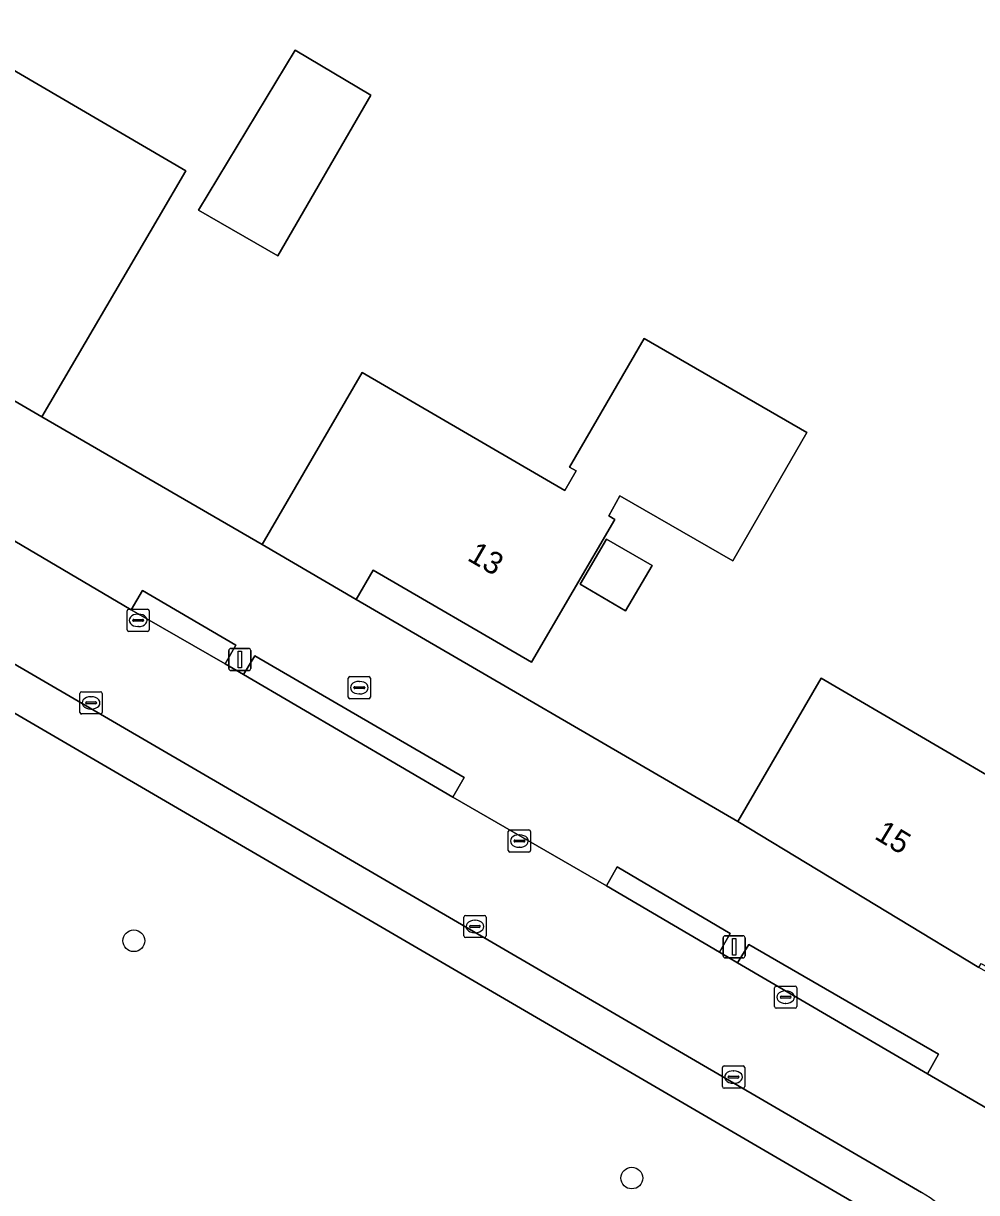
# Model space of a CAD drawing. Extents: x 156502 to 159075, y 384229 to 386100.
# Drawn here: x 157152.9 to 157195.8, y 385865.1 to 385917.7 of the extents above; entities that cross this region are included whole.
import ezdxf

# ---------------------------------------------------------------- set-up
doc = ezdxf.new("R2010")
doc.units = 0
for name, color, linetype in [('IMGEO_Boom', 7, 'Continuous'), ('IMGEO_Erf', 7, 'Continuous'), ('IMGEO_Groenvoorziening', 7, 'Continuous'), ('IMGEO_Haag', 7, 'Continuous'), ('IMGEO_Hek', 7, 'Continuous'), ('IMGEO_Kolk', 7, 'Continuous'), ('IMGEO_Lichtmast', 7, 'Continuous'), ('IMGEO_Pand', 7, 'Continuous'), ('IMGEO_Pand_nummerreeks', 7, 'Continuous'), ('IMGEO_Parkeervlak_open', 7, 'Continuous'), ('IMGEO_Rijbaan_lokaal_open', 7, 'Continuous'), ('IMGEO_Rioolput', 7, 'Continuous'), ('IMGEO_Voetpad_open', 7, 'Continuous')]:
    doc.layers.add(name, color=color, linetype=linetype)

msp = doc.modelspace()

# ---------------------------------------------------------------- linework, layer by layer
at = {"layer": 'IMGEO_Boom'}
for centre in [(157157.909, 385876.436), (157180.326, 385865.757)]:
    msp.add_circle(centre, 0.489, dxfattribs=at)
at = {"layer": 'IMGEO_Erf'}
msp.add_lwpolyline([(157148.886, 385917.721), (157160.243, 385911.082), (157159, 385908.955), (157153.769, 385900.007), (157163.686, 385894.272), (157168.192, 385902.015), (157177.313, 385896.706), (157177.822, 385897.585), (157177.527, 385897.755), (157180.877, 385903.546), (157188.204, 385899.308), (157184.874, 385893.54), (157179.785, 385896.459), (157179.286, 385895.561), (157179.562, 385895.399), (157175.806, 385888.97), (157168.68, 385893.106), (157167.911, 385891.794), (157185.093, 385881.809), (157188.853, 385888.249), (157197.887, 385882.973)], dxfattribs=at)
for points in [[(157164.388, 385907.266), (157160.82, 385909.313), (157165.166, 385916.522), (157168.575, 385914.494)], [(157180.048, 385891.283), (157178.006, 385892.477), (157179.194, 385894.511), (157181.237, 385893.318)]]:
    msp.add_lwpolyline(points, close=True, dxfattribs=at)
at = {"layer": 'IMGEO_Groenvoorziening'}
msp.add_lwpolyline([(157192.564, 385863.354), (157138.908, 385894.614)], dxfattribs=at)
for points in [[(157162.018, 385888.901), (157162.501, 385889.733), (157158.298, 385892.2), (157157.792, 385891.329)], [(157172.275, 385882.9), (157172.777, 385883.778), (157163.363, 385889.258), (157162.851, 385888.415)], [(157184.271, 385875.92), (157184.758, 385876.767), (157179.666, 385879.755), (157179.189, 385878.901)], [(157193.644, 385870.453), (157194.131, 385871.332), (157185.6, 385876.273), (157185.088, 385875.436)]]:
    msp.add_lwpolyline(points, close=True, dxfattribs=at)
at = {"layer": 'IMGEO_Haag'}
for points in [[(157162.018, 385888.901), (157162.501, 385889.733), (157158.298, 385892.2), (157157.792, 385891.329)], [(157172.275, 385882.9), (157172.777, 385883.778), (157163.363, 385889.258), (157162.851, 385888.415)], [(157184.271, 385875.92), (157184.758, 385876.767), (157179.666, 385879.755), (157179.189, 385878.901)], [(157193.644, 385870.453), (157194.131, 385871.332), (157185.6, 385876.273), (157185.088, 385875.436)]]:
    msp.add_lwpolyline(points, close=True, dxfattribs=at)
at = {"layer": 'IMGEO_Hek'}
for points in [[(157153.769, 385900.007), (157163.686, 385894.272)], [(157167.911, 385891.794), (157185.093, 385881.809)]]:
    msp.add_lwpolyline(points, dxfattribs=at)
at = {"layer": 'IMGEO_Kolk'}
for p, q in [((157157.601, 385890.429), (157157.601, 385891.281)), ((157157.676, 385891.355), (157158.528, 385891.355)), ((157157.86, 385890.849), (157157.86, 385890.861)), ((157157.903, 385890.898), (157158.301, 385890.898)), ((157158.089, 385891.135), (157158.114, 385891.135)), ((157158.344, 385890.861), (157158.344, 385890.849)), ((157158.602, 385891.281), (157158.602, 385890.429)), ((157158.528, 385890.355), (157157.676, 385890.355)), ((157158.298, 385890.812), (157157.9, 385890.812)), ((157158.112, 385890.575), (157158.087, 385890.575)), ((157155.482, 385886.714), (157155.482, 385887.566)), ((157155.557, 385887.64), (157156.409, 385887.64)), ((157155.784, 385887.183), (157156.182, 385887.183)), ((157155.97, 385887.42), (157155.995, 385887.42)), ((157156.483, 385887.566), (157156.483, 385886.714)), ((157156.409, 385886.64), (157155.557, 385886.64)), ((157155.741, 385887.134), (157155.741, 385887.146)), ((157156.179, 385887.097), (157155.781, 385887.097)), ((157155.993, 385886.86), (157155.968, 385886.86)), ((157156.225, 385887.146), (157156.225, 385887.134)), ((157174.839, 385881.423), (157175.691, 385881.423)), ((157174.764, 385880.497), (157174.764, 385881.349)), ((157175.023, 385880.917), (157175.023, 385880.929)), ((157175.461, 385880.88), (157175.063, 385880.88)), ((157175.066, 385880.966), (157175.464, 385880.966)), ((157175.252, 385881.203), (157175.277, 385881.203)), ((157175.507, 385880.929), (157175.507, 385880.917)), ((157175.765, 385881.349), (157175.765, 385880.497)), ((157175.691, 385880.423), (157174.839, 385880.423)), ((157175.275, 385880.643), (157175.25, 385880.643)), ((157172.764, 385876.65), (157172.764, 385877.502)), ((157172.839, 385877.576), (157173.691, 385877.576)), ((157173.252, 385877.356), (157173.277, 385877.356)), ((157173.765, 385877.502), (157173.765, 385876.65)), ((157173.023, 385877.07), (157173.023, 385877.082)), ((157173.461, 385877.033), (157173.063, 385877.033)), ((157173.066, 385877.119), (157173.464, 385877.119)), ((157173.275, 385876.796), (157173.25, 385876.796)), ((157173.507, 385877.082), (157173.507, 385877.07)), ((157173.691, 385876.576), (157172.839, 385876.576)), ((157186.751, 385873.47), (157186.751, 385874.322)), ((157186.826, 385874.396), (157187.678, 385874.396)), ((157187.239, 385874.176), (157187.264, 385874.176)), ((157187.752, 385874.322), (157187.752, 385873.47)), ((157187.01, 385873.89), (157187.01, 385873.902)), ((157187.448, 385873.853), (157187.05, 385873.853)), ((157187.053, 385873.939), (157187.451, 385873.939)), ((157187.262, 385873.616), (157187.237, 385873.616)), ((157187.494, 385873.902), (157187.494, 385873.89)), ((157187.678, 385873.396), (157186.826, 385873.396)), ((157184.407, 385869.875), (157184.407, 385870.727)), ((157184.482, 385870.801), (157185.334, 385870.801)), ((157184.709, 385870.344), (157185.107, 385870.344)), ((157184.895, 385870.581), (157184.92, 385870.581)), ((157185.408, 385870.727), (157185.408, 385869.875)), ((157185.334, 385869.801), (157184.482, 385869.801)), ((157184.666, 385870.295), (157184.666, 385870.307)), ((157185.104, 385870.258), (157184.706, 385870.258)), ((157184.918, 385870.021), (157184.893, 385870.021)), ((157185.15, 385870.307), (157185.15, 385870.295))]:
    msp.add_line(p, q, dxfattribs=at)
for points in [[(157157.601, 385890.429), (157157.601, 385891.281)], [(157157.676, 385891.355), (157158.528, 385891.355)], [(157158.602, 385891.281), (157158.602, 385890.429)], [(157158.528, 385890.355), (157157.676, 385890.355)], [(157155.482, 385886.714), (157155.482, 385887.566)], [(157155.557, 385887.64), (157156.409, 385887.64)], [(157156.483, 385887.566), (157156.483, 385886.714)], [(157156.409, 385886.64), (157155.557, 385886.64)], [(157174.839, 385881.423), (157175.691, 385881.423)], [(157174.764, 385880.497), (157174.764, 385881.349)], [(157175.765, 385881.349), (157175.765, 385880.497)], [(157175.691, 385880.423), (157174.839, 385880.423)], [(157172.764, 385876.65), (157172.764, 385877.502)], [(157172.839, 385877.576), (157173.691, 385877.576)], [(157173.765, 385877.502), (157173.765, 385876.65)], [(157173.691, 385876.576), (157172.839, 385876.576)], [(157186.751, 385873.47), (157186.751, 385874.322)], [(157186.826, 385874.396), (157187.678, 385874.396)], [(157187.752, 385874.322), (157187.752, 385873.47)], [(157187.678, 385873.396), (157186.826, 385873.396)], [(157184.407, 385869.875), (157184.407, 385870.727)], [(157184.482, 385870.801), (157185.334, 385870.801)], [(157185.408, 385870.727), (157185.408, 385869.875)], [(157185.334, 385869.801), (157184.482, 385869.801)]]:
    msp.add_lwpolyline(points, dxfattribs=at)
for centre, radius, start, end in [((157157.678, 385891.279), 0.0765, 91.552, 178.448), ((157157.678, 385891.279), 0.0765, 91.552, 178.448), ((157157.9, 385890.858), 0.0403, 85.8775, 175.7526), ((157157.897, 385890.848), 0.0366, 178.938, 274.7102), ((157158.301, 385890.855), 0.043, 264.8664, 352.4533), ((157158.305, 385890.86), 0.0386, 1.7309, 96.639), ((157158.526, 385891.279), 0.0765, 1.552, 88.448), ((157158.526, 385891.279), 0.0765, 1.552, 88.448), ((157157.678, 385890.431), 0.0765, 181.552, 268.448), ((157157.678, 385890.431), 0.0765, 181.552, 268.448), ((157158.526, 385890.431), 0.0765, 271.552, 358.448), ((157158.526, 385890.431), 0.0765, 271.552, 358.448), ((157155.559, 385887.564), 0.0765, 91.552, 178.448), ((157155.559, 385887.564), 0.0765, 91.552, 178.448), ((157155.781, 385887.143), 0.0403, 85.8775, 175.7526), ((157156.186, 385887.145), 0.0386, 1.7309, 96.639), ((157156.407, 385887.564), 0.0765, 1.552, 88.448), ((157156.407, 385887.564), 0.0765, 1.552, 88.448), ((157155.559, 385886.716), 0.0765, 181.552, 268.448), ((157155.559, 385886.716), 0.0765, 181.552, 268.448), ((157155.778, 385887.133), 0.0366, 178.938, 274.7102), ((157156.182, 385887.14), 0.043, 264.8664, 352.4533), ((157156.407, 385886.716), 0.0765, 271.552, 358.448), ((157156.407, 385886.716), 0.0765, 271.552, 358.448), ((157174.841, 385881.347), 0.0765, 91.552, 178.448), ((157174.841, 385881.347), 0.0765, 91.552, 178.448), ((157175.689, 385881.347), 0.0765, 1.552, 88.448), ((157175.689, 385881.347), 0.0765, 1.552, 88.448), ((157175.063, 385880.926), 0.0403, 85.8775, 175.7526), ((157175.06, 385880.916), 0.0366, 178.938, 274.7102), ((157175.464, 385880.923), 0.043, 264.8664, 352.4533), ((157175.468, 385880.928), 0.0386, 1.7309, 96.639), ((157174.841, 385880.499), 0.0765, 181.552, 268.448), ((157174.841, 385880.499), 0.0765, 181.552, 268.448), ((157175.689, 385880.499), 0.0765, 271.552, 358.448), ((157175.689, 385880.499), 0.0765, 271.552, 358.448), ((157172.841, 385877.5), 0.0765, 91.552, 178.448), ((157172.841, 385877.5), 0.0765, 91.552, 178.448), ((157173.689, 385877.5), 0.0765, 1.552, 88.448), ((157173.689, 385877.5), 0.0765, 1.552, 88.448), ((157172.841, 385876.652), 0.0765, 181.552, 268.448), ((157172.841, 385876.652), 0.0765, 181.552, 268.448), ((157173.063, 385877.079), 0.0403, 85.8775, 175.7526), ((157173.06, 385877.069), 0.0366, 178.938, 274.7102), ((157173.464, 385877.076), 0.043, 264.8664, 352.4533), ((157173.468, 385877.081), 0.0386, 1.7309, 96.639), ((157173.689, 385876.652), 0.0765, 271.552, 358.448), ((157173.689, 385876.652), 0.0765, 271.552, 358.448), ((157186.828, 385874.32), 0.0765, 91.552, 178.448), ((157186.828, 385874.32), 0.0765, 91.552, 178.448), ((157187.676, 385874.32), 0.0765, 1.552, 88.448), ((157187.676, 385874.32), 0.0765, 1.552, 88.448), ((157187.05, 385873.899), 0.0403, 85.8775, 175.7526), ((157187.047, 385873.889), 0.0366, 178.938, 274.7102), ((157187.451, 385873.896), 0.043, 264.8664, 352.4533), ((157187.455, 385873.901), 0.0386, 1.7309, 96.639), ((157186.828, 385873.472), 0.0765, 181.552, 268.448), ((157186.828, 385873.472), 0.0765, 181.552, 268.448), ((157187.676, 385873.472), 0.0765, 271.552, 358.448), ((157187.676, 385873.472), 0.0765, 271.552, 358.448), ((157184.484, 385870.725), 0.0765, 91.552, 178.448), ((157184.484, 385870.725), 0.0765, 91.552, 178.448), ((157184.706, 385870.304), 0.0403, 85.8775, 175.7526), ((157185.111, 385870.306), 0.0386, 1.7309, 96.639), ((157185.332, 385870.725), 0.0765, 1.552, 88.448), ((157185.332, 385870.725), 0.0765, 1.552, 88.448), ((157184.484, 385869.877), 0.0765, 181.552, 268.448), ((157184.484, 385869.877), 0.0765, 181.552, 268.448), ((157184.703, 385870.294), 0.0366, 178.938, 274.7102), ((157185.107, 385870.301), 0.043, 264.8664, 352.4533), ((157185.332, 385869.877), 0.0765, 271.552, 358.448), ((157185.332, 385869.877), 0.0765, 271.552, 358.448)]:
    msp.add_arc(centre, radius, start, end, dxfattribs=at)
for centre, major_axis, ratio, start_param, end_param in [((157158.088, 385890.855), (-0.387, 0.002), 0.722429, 4.712389, 7.853982), ((157158.113, 385890.855), (-0.39, 0.002), 0.717154, 1.570796, 4.712389), ((157155.969, 385887.14), (-0.387, 0.002), 0.722429, 4.712389, 7.853982), ((157155.994, 385887.14), (-0.39, 0.002), 0.717154, 1.570796, 4.712389), ((157175.251, 385880.923), (-0.387, 0.002), 0.722429, 4.712389, 7.853982), ((157175.276, 385880.923), (-0.39, 0.002), 0.717154, 1.570796, 4.712389), ((157173.251, 385877.076), (-0.387, 0.002), 0.722429, 4.712389, 7.853982), ((157173.276, 385877.076), (-0.39, 0.002), 0.717154, 1.570796, 4.712389), ((157187.238, 385873.896), (-0.387, 0.002), 0.722429, 4.712389, 7.853982), ((157187.263, 385873.896), (-0.39, 0.002), 0.717154, 1.570796, 4.712389), ((157184.894, 385870.301), (-0.387, 0.002), 0.722429, 4.712389, 7.853982), ((157184.919, 385870.301), (-0.39, 0.002), 0.717154, 1.570796, 4.712389)]:
    msp.add_ellipse(centre, major_axis=major_axis, ratio=ratio, start_param=start_param, end_param=end_param, dxfattribs=at)
at = {"layer": 'IMGEO_Lichtmast'}
for p, q in [((157162.179, 385888.692), (157162.179, 385889.492)), ((157162.179, 385889.492), (157162.179, 385888.692)), ((157162.279, 385889.592), (157163.069, 385889.592)), ((157163.069, 385889.592), (157162.279, 385889.592)), ((157163.169, 385889.492), (157163.169, 385888.692)), ((157163.169, 385888.692), (157163.169, 385889.492)), ((157163.069, 385888.592), (157162.279, 385888.592)), ((157162.279, 385888.592), (157163.069, 385888.592)), ((157184.534, 385876.66), (157185.324, 385876.66)), ((157185.324, 385876.66), (157184.534, 385876.66)), ((157184.434, 385875.76), (157184.434, 385876.56)), ((157184.434, 385876.56), (157184.434, 385875.76)), ((157185.424, 385876.56), (157185.424, 385875.76)), ((157185.424, 385875.76), (157185.424, 385876.56)), ((157185.324, 385875.66), (157184.534, 385875.66)), ((157184.534, 385875.66), (157185.324, 385875.66))]:
    msp.add_line(p, q, dxfattribs=at)
for points in [[(157162.599, 385889.467), (157162.749, 385889.467), (157162.749, 385888.717), (157162.599, 385888.717), (157162.599, 385889.467)], [(157184.854, 385876.535), (157185.004, 385876.535), (157185.004, 385875.785), (157184.854, 385875.785), (157184.854, 385876.535)]]:
    msp.add_lwpolyline(points, dxfattribs=at)
for centre, start, end in [((157162.279, 385889.492), 90, 180), ((157162.279, 385889.492), 90, 180), ((157163.069, 385889.492), 0, 90), ((157163.069, 385889.492), 360, 90), ((157162.279, 385888.692), 180, 270), ((157162.279, 385888.692), 180, 270), ((157163.069, 385888.692), 270, 0), ((157163.069, 385888.692), 270, 0), ((157184.534, 385876.56), 90, 180), ((157184.534, 385876.56), 90, 180), ((157185.324, 385876.56), 0, 90), ((157185.324, 385876.56), 360, 90), ((157184.534, 385875.76), 180, 270), ((157184.534, 385875.76), 180, 270), ((157185.324, 385875.76), 270, 0), ((157185.324, 385875.76), 270, 0)]:
    msp.add_arc(centre, 0.1, start, end, dxfattribs=at)
at = {"layer": 'IMGEO_Pand'}
for points in [[(157159, 385908.955), (157160.243, 385911.082), (157148.886, 385917.721), (157146.148, 385913.037), (157142.433, 385906.61), (157153.769, 385900.007)], [(157164.388, 385907.266), (157168.575, 385914.494), (157165.166, 385916.522), (157160.82, 385909.313)], [(157163.686, 385894.272), (157167.911, 385891.794), (157168.68, 385893.106), (157175.806, 385888.97), (157179.562, 385895.399), (157179.286, 385895.561), (157179.785, 385896.459), (157184.874, 385893.54), (157188.204, 385899.308), (157180.877, 385903.546), (157177.527, 385897.755), (157177.822, 385897.585), (157177.313, 385896.706), (157168.192, 385902.015)], [(157179.194, 385894.511), (157178.006, 385892.477), (157180.048, 385891.283), (157181.237, 385893.318)], [(157195.952, 385875.233), (157196.06, 385875.413), (157196.439, 385875.192), (157200.198, 385881.649), (157199.904, 385881.82), (157200.407, 385882.684), (157205.225, 385879.893), (157209.465, 385887.215), (157202.417, 385891.356), (157198.106, 385884.017), (157198.399, 385883.845), (157197.887, 385882.973), (157188.853, 385888.249), (157185.093, 385881.809)]]:
    msp.add_lwpolyline(points, close=True, dxfattribs=at)
at = {"layer": 'IMGEO_Parkeervlak_open'}
for points in [[(157193.373, 385865.1), (157139.856, 385896.261)], [(157138.908, 385894.614), (157192.564, 385863.354)]]:
    msp.add_lwpolyline(points, dxfattribs=at)
msp.add_arc((157191.291, 385861.169), 4.448, 332.2348, 62.0914, dxfattribs=at)
at = {"layer": 'IMGEO_Rijbaan_lokaal_open'}
for points in [[(157172.275, 385882.9), (157162.851, 385888.415), (157162.018, 385888.901), (157157.792, 385891.329), (157151.032, 385895.3), (157141.609, 385900.746), (157140.788, 385901.231), (157136.535, 385903.695), (157134.317, 385905), (157131.896, 385900.891), (157126.435, 385891.435), (157125.704, 385890.195), (157117.969, 385876.968), (157117.795, 385876.679), (157112.461, 385867.56), (157109.666, 385862.678)], [(157139.856, 385896.261), (157193.373, 385865.1)], [(157205.703, 385857.935), (157250.457, 385831.882), (157250.702, 385832.309), (157252.582, 385835.588), (157249.263, 385837.527), (157249.511, 385837.937), (157247.026, 385839.395), (157246.178, 385839.897), (157241.947, 385842.373), (157235.934, 385845.88), (157226.506, 385851.343), (157225.619, 385851.871), (157222.254, 385853.823), (157216.161, 385857.317), (157205.901, 385863.335), (157205.084, 385863.813), (157201.692, 385865.761), (157193.644, 385870.453), (157185.088, 385875.436), (157184.271, 385875.92), (157179.189, 385878.901), (157172.275, 385882.9)]]:
    msp.add_lwpolyline(points, dxfattribs=at)
msp.add_arc((157191.291, 385861.169), 4.448, 332.2348, 62.0914, dxfattribs=at)
at = {"layer": 'IMGEO_Rioolput'}
for p, q in [((157167.559, 385887.399), (157167.559, 385888.251)), ((157167.634, 385888.325), (157168.486, 385888.325)), ((157168.56, 385888.251), (157168.56, 385887.399)), ((157167.818, 385887.819), (157167.818, 385887.831)), ((157168.256, 385887.782), (157167.858, 385887.782)), ((157167.861, 385887.868), (157168.259, 385887.868)), ((157168.047, 385888.105), (157168.072, 385888.105)), ((157168.302, 385887.831), (157168.302, 385887.819)), ((157168.486, 385887.325), (157167.634, 385887.325)), ((157168.07, 385887.545), (157168.045, 385887.545))]:
    msp.add_line(p, q, dxfattribs=at)
for points in [[(157167.559, 385887.399), (157167.559, 385888.251)], [(157167.634, 385888.325), (157168.486, 385888.325)], [(157168.56, 385888.251), (157168.56, 385887.399)], [(157168.486, 385887.325), (157167.634, 385887.325)]]:
    msp.add_lwpolyline(points, dxfattribs=at)
for centre, radius, start, end in [((157167.636, 385888.249), 0.0765, 91.552, 178.448), ((157167.636, 385888.249), 0.0765, 91.552, 178.448), ((157168.484, 385888.249), 0.0765, 1.552, 88.448), ((157168.484, 385888.249), 0.0765, 1.552, 88.448), ((157167.858, 385887.828), 0.0403, 85.8775, 175.7526), ((157167.855, 385887.818), 0.0366, 178.938, 274.7102), ((157168.259, 385887.825), 0.043, 264.8664, 352.4533), ((157168.263, 385887.83), 0.0386, 1.7309, 96.639), ((157167.636, 385887.401), 0.0765, 181.552, 268.448), ((157167.636, 385887.401), 0.0765, 181.552, 268.448), ((157168.484, 385887.401), 0.0765, 271.552, 358.448), ((157168.484, 385887.401), 0.0765, 271.552, 358.448)]:
    msp.add_arc(centre, radius, start, end, dxfattribs=at)
for centre, major_axis, ratio, start_param, end_param in [((157168.046, 385887.825), (-0.387, 0.002), 0.722429, 4.712389, 7.853982), ((157168.071, 385887.825), (-0.39, 0.002), 0.717154, 1.570796, 4.712389)]:
    msp.add_ellipse(centre, major_axis=major_axis, ratio=ratio, start_param=start_param, end_param=end_param, dxfattribs=at)
at = {"layer": 'IMGEO_Voetpad_open'}
for points in [[(157226.078, 385857.975), (157218.954, 385862.085), (157207.627, 385868.664), (157195.952, 385875.233), (157185.093, 385881.809), (157167.911, 385891.794), (157163.686, 385894.272), (157153.769, 385900.007), (157142.433, 385906.61), (157136.759, 385909.918), (157130.978, 385913.286), (157125.953, 385904.606), (157125.678, 385904.13), (157120.993, 385896.017), (157120.156, 385894.568), (157117.68, 385890.28), (157119.669, 385889.108)], [(157151.032, 385895.3), (157157.792, 385891.329), (157158.298, 385892.2), (157162.501, 385889.733), (157162.018, 385888.901), (157162.851, 385888.415), (157163.363, 385889.258), (157172.777, 385883.778), (157172.275, 385882.9), (157179.189, 385878.901), (157179.666, 385879.755), (157184.758, 385876.767), (157184.271, 385875.92), (157185.088, 385875.436), (157185.6, 385876.273), (157194.131, 385871.332), (157193.644, 385870.453), (157201.692, 385865.761)]]:
    msp.add_lwpolyline(points, dxfattribs=at)

# ---------------------------------------------------------------- texts
at = {"layer": 'IMGEO_Pand_nummerreeks'}
for s, rotation, p in [('13', 329.8687, (157172.874, 385893.585)), ('15', 328.8006, (157191.201, 385881.056))]:
    msp.add_text(s, height=1, rotation=rotation, dxfattribs=at).set_placement(p)

doc.saveas('drawing.dxf')
